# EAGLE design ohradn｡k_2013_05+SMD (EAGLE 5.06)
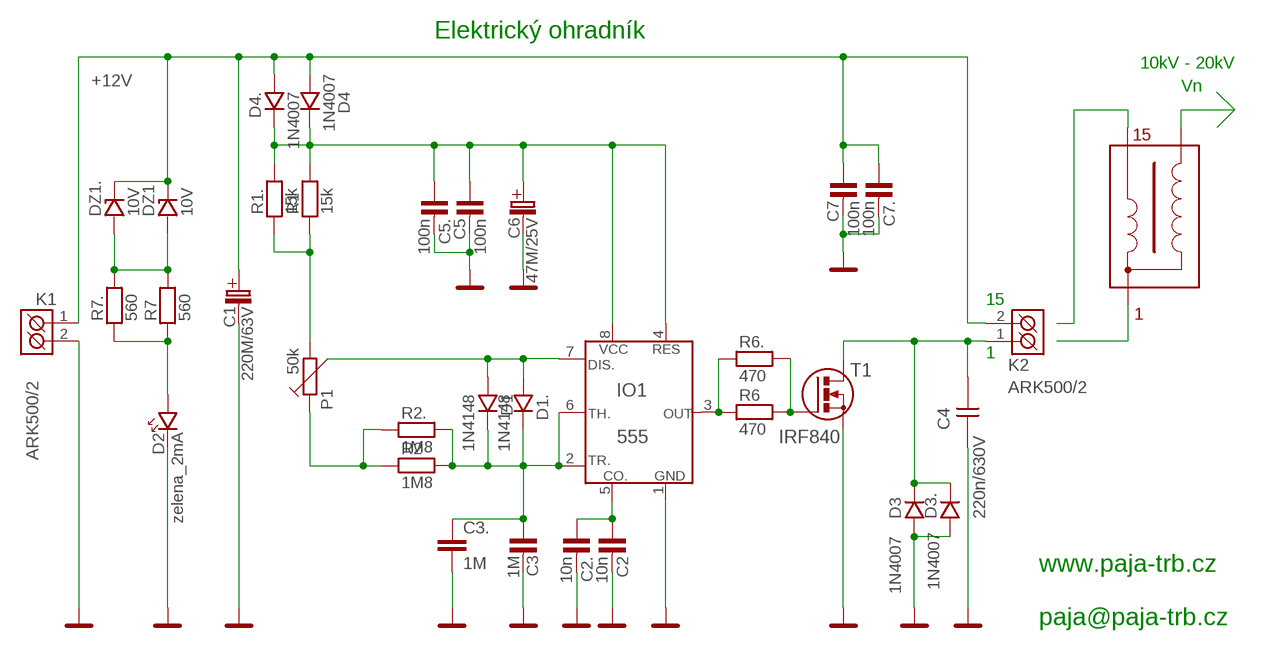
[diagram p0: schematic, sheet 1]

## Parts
C1  220M/63V  [C_EL_5]
C2  10n  C-KERAMIK_5  [C-5]
C2.  10n  C-KERAMIK_SMD_1206  [1206]
C3  1M  1M-K/63V  [RM5_5,0]
C3.  1M  C-EUC2225K  [C2225K]
C4  220n/630V  CFAC-22,5  [CFAC-22]
C5  100n  C-KERAMIK_5  [C-5]
C5.  100n  C-KERAMIK_SMD_1206  [1206]
C6  47M/25V  [C_EL_2]
C7  100n  C-KERAMIK_5  [C-5]
C7.  100n  C-KERAMIK_SMD_1206  [1206]
D1  1N4148  1N4148_7,5  [D-7,5]
D1.  1N4148  1N4148_SMD_SOD80  [SOD-80]
D2  zelena_2mA  LED_5  [LED_5]
D3  1N4007  1N4007_10  [D-10]
D3.  1N4007  1N4007_SM-1  [SM-1]
D4  1N4007  1N4007_10  [D-10]
D4.  1N4007  1N4007_SM-1  [SM-1]
DZ1  10V  D-ZENEROVA_0,5W_BZX83V  [D-7,5]
DZ1.  10V  D-ZENEROVA_0,5W_BZV55C_SMD  [SOD-80]
IO1  555  [DIL8]
K1  ARK500/2  [ARK500/2]
K2  ARK500/2  [ARK500/2]
P1  50k  TRIMRPT6V  [PT6V]
R1  15k  R_7,5  [R-7,5]
R1.  15k  R_SMD_1206  [1206]
R2  1M8  R_7,5  [R-7,5]
R2.  1M8  R_SMD_1206  [1206]
R6  470  R_7,5  [R-7,5]
R6.  470  R_SMD_1206  [1206]
R7  560  R_7,5  [R-7,5]
R7.  560  R_SMD_1206  [1206]
T1  IRF840  BUZ10_STOJ  [TO-220S]

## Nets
+12V: C1.C+(C_EL+) C7.1 C7..1 D4..A D4.A DZ1..K DZ1.K K1.1(K1) K2.2(K2)
+NAP: C5.1 C5..1 C6.C+(C_EL+) D4..K D4.K IO1.4(RES) IO1.8(VCC) R1.2 R1..2
GND: C1.C-(C_EL-) C2.2 C2..2 C3.2 C3..2 C4.1 C5.2 C5..2 C6.C-(C_EL-) C7.2 C7..2 D2.K D3..A D3.A IO1.1(GND) K1.2(K2) T1.3(S)
N$2: P1.1 R2.1 R2..1
N$3: P1.2 R1.1 R1..1
N$6: C2.1 C2..1 IO1.5(CO.)
N$7: IO1.3(OUT) R6.1 R6..1
N$8: R6.2 R6..2 T1.1(G)
N$9: D1..A D1.A IO1.7(DIS.) P1.3
N$10: C3.1 C3..1 D1..K D1.K IO1.2(TR.) IO1.6(TH.) R2.2 R2..2
N$11: D2.A R7.1 R7..1
N$12: DZ1..A DZ1.A R7.2 R7..2
OUT: C4.2 D3..K D3.K K2.1(K1) T1.2(D)

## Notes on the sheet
- Elektrický ohradník
- 10kV - 20kV
- Vn
- 15
- 15 | 1
- 1
- www.paja-trb.cz
- paja@paja-trb.cz

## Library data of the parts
C1 = #PaJa_C-el:220M/63V
C2 C5 C7 = #PaJa_20:C-KERAMIK: Kondenzator - keramicky
C2. C5. C7. = #PaJa_31:C-KERAMIK: Kondenzator - keramicky
C3 = #PaJa_C-folie:1M-K/63V
C3. = rcl:C-EU: CAPACITOR, European symbol
C4 = #_GM99:CFAC-22,5
C6 = #PaJa_C-el:47M/25V
D1 D1. = #PaJa_20:1N4148: Univerzalni dioda - 0,15A, 75V
D2 = #PaJa_20:LED: LED - jednobarevna
D3 D4 = #PaJa_20:1N4007: Usmernovaci dioda - 1A, 1000V
D3. D4. = #PaJa_31:1N4007: Usmernovaci dioda - 1A, 1000V
DZ1 DZ1. = #PaJa_20:D-ZENEROVA: Zenerova dioda
IO1 = #PaJa_20:555: IO - Casovac 555
K1 K2 = #PaJa_20:ARK500/2: Svorkovnice - roztec 5mm - dvojita
P1 = #PaJa_31:TRIMR: Trimr
R1 R1. R2 R2. R6 R6. R7 R7. = #PaJa_20:R: Rezistor
T1 = #PaJa_20:BUZ10: N-Channel Enhancement MOSFET 50V; 20A; 0,080Ohm

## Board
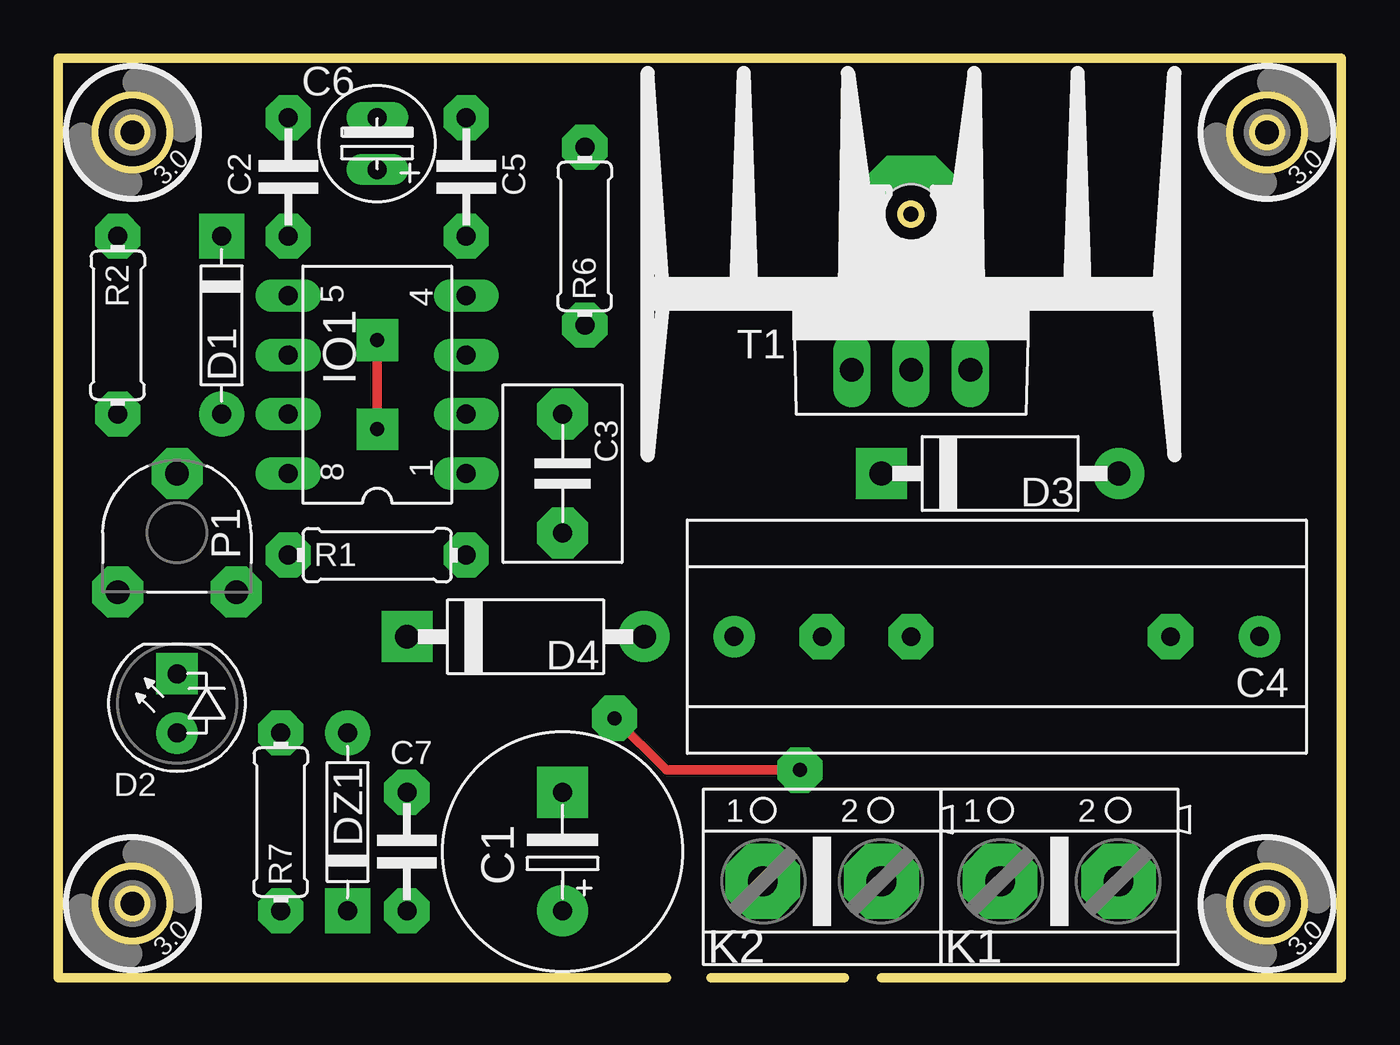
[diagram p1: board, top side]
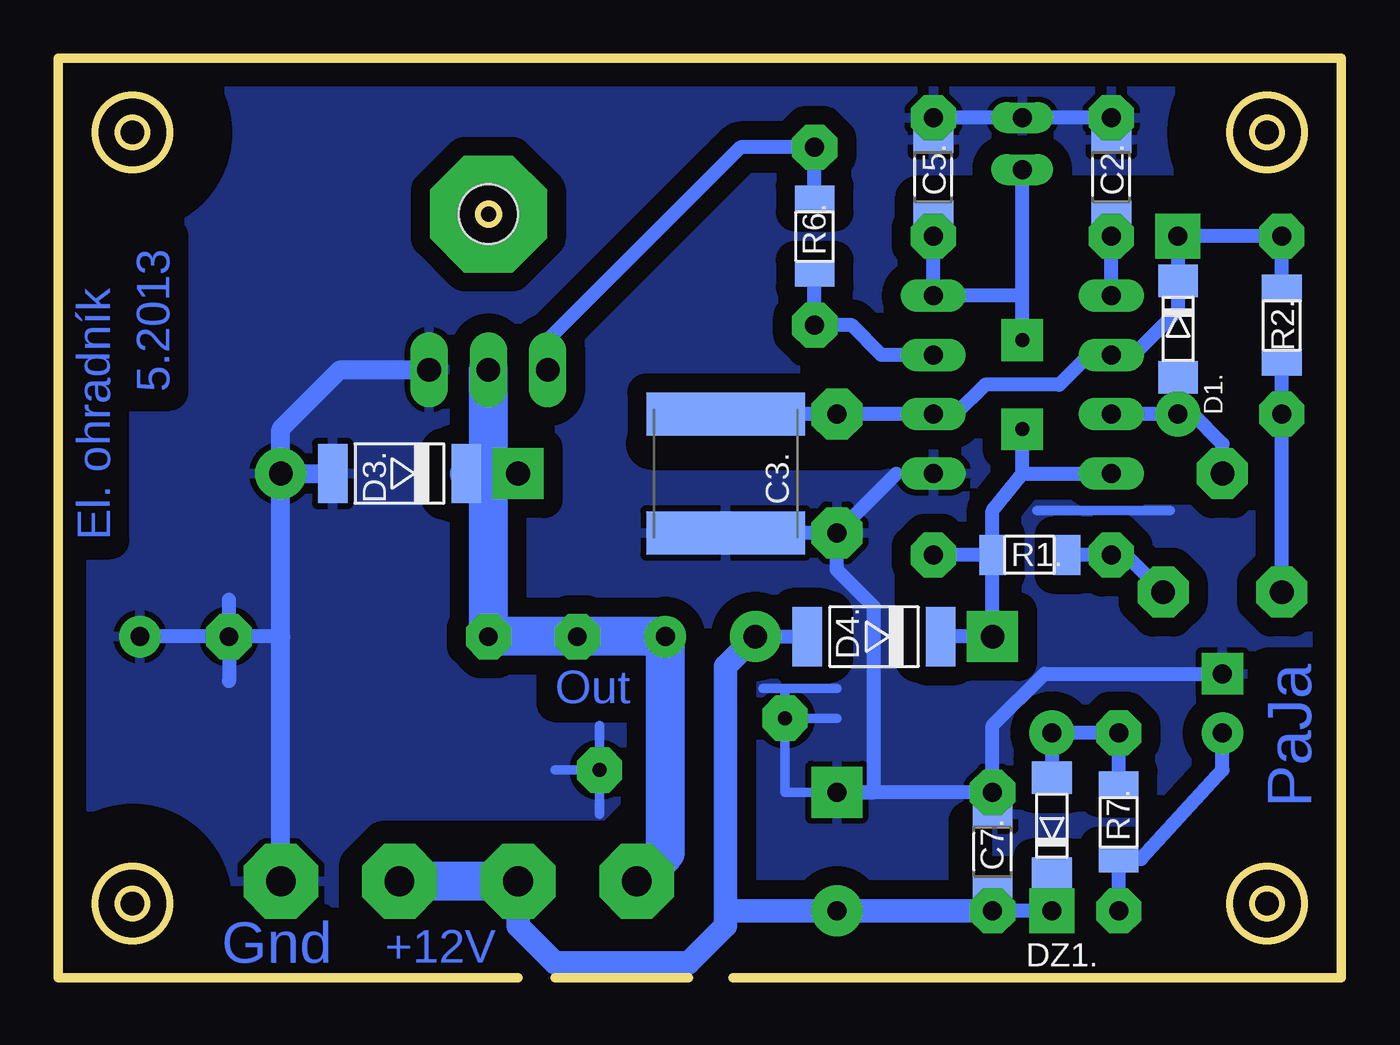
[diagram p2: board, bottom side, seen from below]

Size 54.93 x 39.37 mm. Coordinates in mm from the lower left corner, seen from the top.
Outline: 26.04,0 0,0 0,5.71
Outline: 0,5.71 0,6.03
Outline: 0,5.71 0,39.37 54.93,39.37 54.93,0 35.24,0
Outline: 27.94,0 33.66,0
Outline: circle at 36.51,32.7 radius 0.45
Copper layers (1*16): Top 0.035mm / dielectric 1.5mm / Bottom 0.035mm
Design rules "default": minimum track width 10mil, minimum drill 24mil, track to track 8mil, track to pad 8mil, pad to pad 8mil, via to via 8mil, smd to smd 8mil, copper to edge 40mil, drill to drill 8mil, minimum pad ring 10mil, minimum via ring 8mil, stop-mask expansion 4mil, vias tented up to drill 0mil, thermal gap 10mil
bRestrict: area 47.3,14.3 to 47.9,14.9; area 31.4,8.6 to 32.1,9.2; area 23.5,10.8 to 24.1,11.4; 11 lines

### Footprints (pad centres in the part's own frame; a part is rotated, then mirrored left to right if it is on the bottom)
C_EL_5 = drill 0.813 pad 2.184 round: C+ -2.54,0 | drill 0.813 pad 2.184 square: C- 2.54,0
C-5 = drill 0.813 pad 1.93 octagon: 1 -2.54,0; 2 2.54,0
1206 = smd 1.143 x 1.702: 1 -1.587,0; 2 1.587,0
RM5_5,0 = drill 0.813 pad 2.184 octagon: 1 -2.54,0; 2 2.54,0
C2225K = smd 1.85 x 6.8: 1 -2.55,0; 2 2.55,0
CFAC-22 = drill 0.813 pad 1.778 round: 1 0,0; 2 22.5,0
C_EL_2 = drill 0.813 pad 1.27 long: C+ 0,0; C- 2.223,0
D-7,5 = drill 0.813 pad 1.93 round: A -3.81,0 | drill 0.813 pad 1.93 square: K 3.81,0
SOD-80 = smd 1.397 x 1.702: A 1.905,0; K -2.223,0
LED_5 = drill 0.813 pad 1.778 round: A -1.27,0 | drill 0.813 pad 1.778 square: K 1.27,0
D-10 = drill 1.016 pad 2.184 round: A -5.08,0 | drill 1.016 pad 2.184 square: K 5.08,0
SM-1 = smd 1.27 x 2.54: A 2.857,0; K -2.857,0
DIL8 = drill 0.813 pad 1.4 long: 1 -3.81,-3.81; 2 -1.27,-3.81; 3 1.27,-3.81; 4 3.81,-3.81; 5 3.81,3.81; 6 1.27,3.81; 7 -1.27,3.81; 8 -3.81,3.81
ARK500/2 = drill 1.27 pad 3.2 octagon: 1 -2.54,0; 2 2.54,0
PT6V = drill 1.016 pad 2.184 octagon: 1 -2.54,-2.54; 2 2.54,-2.54; 3 0,2.54
R-7,5 = drill 0.813 pad 1.93 octagon: 1 -3.81,0; 2 3.81,0
TO-220S = drill 1.016 pad 1.6 long: 1 -2.54,0; 2 0,0; 3 2.54,0
CH_V7142 = hole 2.54: 0,0
HOLE_3,0 = hole 3.2: 0,0

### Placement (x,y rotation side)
C1  21.59,5.4 90 top
C2  9.84,34.29 90 top
C2.  9.84,34.29 90 bottom
C3  21.59,21.59 270 top
C3.  26.35,21.59 270 bottom
C4  51.44,14.61 180 top
C5  17.46,34.29 90 top
C5.  17.46,34.29 90 bottom
C6  13.65,34.61 90 top
C7  14.92,5.4 90 top
C7.  14.92,5.4 90 bottom
D1  6.99,27.94 90 top
D1.  6.99,27.62 270 bottom
D2  5.08,11.75 90 top
D3  40.32,21.59 180 top
D3.  40.32,21.59 180 bottom
D4  20,14.61 180 top
D4.  20,14.61 180 bottom
DZ1  12.38,6.67 270 top
DZ1.  12.38,6.67 90 bottom
IO1  13.65,25.4 90 top
K1  42.86,4.13 0 top
K2  32.7,4.13 0 top
P1  5.08,19.05 0 top
R1  13.65,18.1 0 top
R1.  13.34,18.1 180 bottom
R2  2.54,27.94 90 top
R2.  2.54,27.94 90 bottom
R6  22.54,31.75 90 top
R6.  22.54,31.75 90 bottom
R7  9.53,6.67 90 top
R7.  9.53,6.67 90 bottom
T1  36.51,26.04 0 top
U$1  [CH_V7142]  36.51,32.7 0 top
U$2  [HOLE_3,0]  51.75,3.17 0 top
U$3  [HOLE_3,0]  51.75,36.2 0 top
U$4  [HOLE_3,0]  3.17,3.17 0 top
U$5  [HOLE_3,0]  3.17,36.2 0 top

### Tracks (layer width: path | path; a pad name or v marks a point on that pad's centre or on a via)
+12V
  Bottom 0.61: C7..1 C7.1 DZ1.K DZ1..K | D4.A D4..A D4.A
  Bottom 1.016: K2.2 35.24,2.22 33.66,0.64 27.94,0.64 26.35,2.22 26.35,2.86 | C7.1 C1.C+ 26.35,2.86 | D4.A 26.35,13.34 26.35,2.86
  Bottom 1.676: K2.2 K1.1
+NAP  (via drill 0.6 pad 1.78)
  Top 0.406: v13.65,23.5 v13.65,27.3
  Bottom 0.61: D4.K D4..K D4.K | C5..1 C5.1 IO1.4 13.65,29.21 | R1..2 R1.2 | v13.65,27.3 13.65,29.21 | 13.65,29.21 C6.C+ | 13.65,21.59 IO1.8 | 13.65,21.59 v13.65,23.5 | R1..2 14.92,20 13.65,21.59 | D4.K R1..2
GND  (via drill 0.6 pad 1.93, 0.8 pad 1.93)
  Top 0.406: v23.81,11.11 26.04,8.89 v31.75,8.89
  Bottom 0.406: C2.2 C6.C- | 19.05,21.59 IO1.1 | C3..2 | 7.3,20 13.02,20 | v23.81,11.11 21.59,11.11 | v23.81,11.11 23.81,7.94 C1.C- | v31.75,8.89 31.75,6.99 | v31.75,8.89 31.75,10.79 | v31.75,8.89 33.66,8.89 | v23.81,11.11 23.81,12.38 | 23.81,12.38 24.77,12.38 | 23.81,12.38 21.59,12.38
  Bottom 0.61: v47.62,14.61 C4.1 | C6.C- C5.2 C5..2 | C6.C- C2.2 C2..2 | C6.C- 13.66,37.15 | C7.2 C1.C- 20,7.94 20,15.88 21.59,17.46 C3.2 | C3.2 19.05,21.59 | C3.2 C3..2 | D2.K 12.7,13.02 14.92,10.79 C7.2 | C7..2 C7.2 | 45.4,14.61 v47.62,14.61 | v47.62,14.61 47.62,16.19 | v47.62,14.61 47.62,12.7
  Bottom 0.813: T1.3 42.86,26.04 45.4,23.5 D3.A | D3.A D3..A | K1.2 45.4,14.61 D3.A
  pour Bottom (isolate 0.813): 0,0 0,39.37 54.93,39.37 54.93,0
N$2
  Bottom 0.61: R2..1 R2.1 P1.1
N$3
  Bottom 0.61: R1..1 R1.1 9.21,18.1 P1.2
N$6
  Bottom 0.61: C2..1 C2.1 IO1.5
N$7
  Bottom 0.61: IO1.3 19.68,26.67 20.95,27.94 R6.1 R6..1
N$8
  Bottom 0.61: R6..2 R6.2 25.72,35.56 33.97,27.3 T1.1
N$9
  Bottom 0.61: D1.A IO1.7 | D1.A D1..A | P1.3 5.08,22.86 6.35,24.13 D1.A
N$10
  Bottom 0.406: C3..1
  Bottom 0.61: C3..1 C3.1 IO1.2 16.51,24.13 15.24,25.4 12.06,25.4 10.79,26.67 IO1.6 8.89,26.67 6.99,28.57 D1..K D1.K R2.2 R2..2
N$11
  Bottom 0.61: R7.1 R7..1 8.57,5.08 5.08,8.89 D2.A
N$12
  Bottom 0.61: DZ1..A DZ1.A R7.2 R7..2
N$14  (via drill 2.5 pad 5)
  other vias: 36.51,32.7
OUT  (via drill 0.8 pad 1.93)
  Bottom 1.422: D3.K 36.51,21.59 D3..K
  Bottom 1.676: T1.2 36.51,21.59 v36.51,14.61 v32.7,14.61 C4.2 28.93,5.36 K2.1

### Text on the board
Bottom: 5.2013 | El. ohradník | Out | PaJa | +12V | Gnd
wago-cervena: 0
